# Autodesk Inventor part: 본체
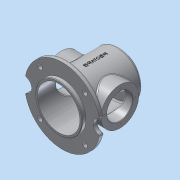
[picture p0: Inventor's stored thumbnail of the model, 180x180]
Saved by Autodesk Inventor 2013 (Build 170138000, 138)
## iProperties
Created: 2018-04
Part Number: 본체
Material: 알루미늄 6061
Document SubType Name: Modeling
Designer: dgall
Density: 2.71 g/cm^3
Mass: 1151.24 g
Surface Area: 1200.36 cm^2
Volume: 424.812 cm^3
Author: dgall
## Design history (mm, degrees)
sketch "스케치1"
  geometry: L1 (0, 64)-(0, -64); L2 (0, 64)-(-50, 64); L3 (-50, 64)-(-50, -64); L4 (0, 56)-(-45, 56); L5 (-45, 56)-(-45, -64); L6 (-50, -64)-(-45, -64); 2 further points
  constraints: 12 end point, 4 perpendicular, 2 horizontal alignment, 1 coincident, 1 midpoint, 1 parallel, 1 point on line, 1 vertical
  dimensions: "d0" = 128 distance of L1.start L1.end; "d2" = 100 diameter of L3 L1; "d3" = 8 distance between parallel lines of L4 L2; "d4" = 90 diameter of L5 L1
revolve "회전1" sketch "스케치1" stored, may be unused: angle "d5" = 90 deg
sketch "스케치2"
  geometry: C1 r 50 at (0, 0) reference; C2 r 40 at (0, 0)
  constraints: 1 centre point, 1 coincident
  dimensions: "d6" = 80 diameter of C2
extrude "돌출1" join sketch "스케치2" distance "d7" = 5; taper "d8" = 0 deg
hole "구멍1" diameter "d11" = 54; stored, may be unused: countersink angle "d15" = 90 deg, drill point angle "d17" = 0 deg; dims "d9" = 10, "d10" = 10, "d12" = 6, "d13" = 4, "d14" = 2, "d16" = 13
node "작업 평면1"
sketch "스케치3"
  geometry: L1 (-64, -50)-(-64, 50) reference; C1 r 40 at (4, 0); 1 further point
  constraints: 1 centre point, 1 horizontal alignment
  dimensions: "d19" = 80 diameter of C1; "d20" = 68 distance from line of L1 C1.centre
extrude "돌출2" join sketch "스케치3" stored distance "d21" = 10; taper "d22" = 0 deg
hole "구멍2" diameter "d25" = 54; stored, may be unused: countersink angle "d29" = 90 deg, drill point angle "d31" = 0 deg; dims "d23" = 10, "d24" = 10, "d26" = 6, "d27" = 4, "d28" = 2, "d30" = 30
sketch "스케치4"
  geometry: C1 r 27 at (0, 0) reference; 2 further points
  constraints: 1 vertical alignment
  dimensions: "d32" = 32.5 distance of C1.centre point (0, 32.5)
hole "구멍3" sketch "스케치4" at (0, 32.5) diameter "d33" = 3.242; stored, may be unused: countersink angle "d37" = 90 deg, drill point angle "d39" = 118 deg; dims "d34" = 8, "d35" = 4, "d36" = 2, "d38" = 10
sketch "스케치5"
  geometry: C1 r 27 at (0, 0) reference; 1 further point
  constraints: 1 vertical alignment
  dimensions: "d43" = 32.5 distance of C1.centre point (0, 32.5)
hole "구멍4" sketch "스케치5" at (0, 32.5) diameter "d44" = 3.242; stored, may be unused: countersink angle "d48" = 90 deg, drill point angle "d50" = 118 deg; dims "d45" = 8, "d46" = 4, "d47" = 2, "d49" = 10
chamfer "모따기1" distance "d54" = 1; stored, may be unused: second distance "d55" = 2, angle "d56" = 45 deg
fillet "모깎기1" dims "d57" = 5
fillet "모깎기2" dims "d58" = 3
node "작업 평면2"
sketch "스케치6"
  geometry: C1 r 50 at (0, 0) reference; C2 r 45 at (0, 0) reference; C3 r 80 at (0, 0); 1 further point
  constraints: 1 centre point, 1 coincident
  dimensions: "d60" = 160 diameter of C3
extrude "돌출3" join sketch "스케치6" distance "d63" = 10; taper "d64" = 0 deg
sketch "스케치7"
  geometry: C1 r 50 at (0, 0) reference; A1 r 80 centre (0, 0) between (-80, 0) and (80, 0) reference; A2 r 15 centre (-80, 0) between (-78.594, -14.934) and (-78.594, 14.934); A3 r 15 centre (80, 0) between (78.594, 14.934) and (78.594, -14.934)
  constraints: 10 point on circle, 2 centre point, 2 horizontal alignment
  dimensions: "d65" = 30 diameter of A2; "d66" = 30 diameter of A3
extrude "돌출4" cut sketch "스케치7" stored distance "d67" = 8; taper "d68" = 0 deg
fillet "모깎기3" dims "d69" = 3
fillet "모깎기4" dims "d70" = 3
sketch "스케치8" dims "d71" = 135
  geometry: L1 (0, 0)-(-80, 0); L2 (0, 0)-(-47.73, 47.73); C1 r 5 at (-47.73, 47.73); A1 r 18 centre (-80, 0) between (-75.031, -17.301) and (-75.031, 17.301) reference; A2 r 77 centre (0, 0) between (-75.031, -17.301) and (75.031, -17.301) reference; 1 further point
  constraints: 4 end point, 2 coincident, 1 centre point, 1 horizontal, 3 other
  dimensions: "d73" = 45 deg angle of L2 L1; "d75" = 10 diameter of C1
extrude "돌출5" cut sketch "스케치8" stored distance "d76" = 8; taper "d77" = 0 deg
chamfer "모따기2" distance "d81" = 1; stored, may be unused: second distance "d82" = 2, angle "d83" = 45 deg
node "작업 평면3"
sketch "스케치9"
  geometry: L1 (49, -64)-(-49, -64) reference; L2 (77.955, -56)-(-77.955, -56) reference; 2 further points
  constraints: 1 vertical alignment, 1 other
  dimensions: "d84" = 70 distance from line of point (0, 14) L2
feature "엠보싱1" sketch "스케치9" dims "d85" = 0.5, "d86" = 0
node "솔리드1"
mirror "대칭1"
pattern_circular "원형 패턴1" dims angle "d41" = 360 deg
mirror "대칭2"
pattern_circular "원형 패턴2" dims angle "d52" = 360 deg
pattern_circular "원형 패턴3" dims angle "d79" = 360 deg
node "절단 모서리 투영1"
other parameters: "d18" = 62, "d59" = -8
